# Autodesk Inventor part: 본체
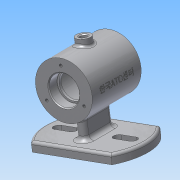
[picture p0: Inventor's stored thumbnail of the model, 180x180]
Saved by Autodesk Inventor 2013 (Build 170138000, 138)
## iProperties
Created: 2017-12
Part Number: 본체
Material: 알루미늄 6061
Document SubType Name: Modeling
Designer: Administrator
Density: 2.71 g/cm^3
Mass: 467.723 g
Surface Area: 486.557 cm^2
Volume: 172.592 cm^3
Author: Administrator
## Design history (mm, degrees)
sketch "스케치1"
  geometry: L1 (-35, -42.426)-(-35, 42.426); L2 (35, -42.426)-(35, 42.426); L3 (0, 0)-(0, 71.634); L4 (5, -40)-(5, -24); L5 (-5, -40)-(-5, -24); L6 (-1.738, 0)-(67.006, 0); L7 (5, 40)-(5, 24); L8 (-5, 40)-(-5, 24); L9 (-15, -5)-(15, -5); L10 (-15, 5)-(15, 5); A1 r 55 centre (0, 0) between (-35, -42.426) and (35, -42.426); A2 r 55 centre (0, 0) between (35, 42.426) and (-35, 42.426); A3 r 5 centre (0, -40) between (-5, -40) and (5, -40); A4 r 5 centre (0, -24) between (5, -24) and (-5, -24); A5 r 5 centre (0, 40) between (5, 40) and (-5, 40); A6 r 5 centre (0, 24) between (-5, 24) and (5, 24); A7 r 5 centre (-15, 0) between (-15, 5) and (-15, -5); A8 r 5 centre (15, 0) between (15, -5) and (15, 5); 1 further point
  constraints: 20 end point, 16 point on circle, 8 centre point, 7 symmetric about line, 4 parallel, 4 tangent, 2 coincident, 2 perpendicular, 1 point on line, 1 vertical, 3 other
  dimensions: "d2" = 70 distance between parallel lines of L2 L1; "d3" = 0 horizontal distance of A4.centre A3.centre; "d4" = 10 diameter of A3; "d5" = 10 diameter of A4; "d6" = 24 distance of point (0, 0) A4.centre; "d7" = 16 distance of A4.centre A3.centre; "d8" = 0 vertical distance of point (0, 0) A7.centre; "d9" = 10 diameter of A7; "d10" = 10 diameter of A8; "d11" = 30 distance of A7.centre A8.centre
extrude "돌출1" new body sketch "스케치1" distance "d12" = 10; taper "d13" = 0 deg
extrude "돌출2" join sketch "스케치1" distance "d14" = 50; taper "d15" = 0 deg
node "스케치2"
sketch "스케치3"
  geometry: L1 (-35, 42.426)-(-35, -42.426) reference; L2 (-5, 40)-(-5, 24); L3 (5, 40)-(5, 24); L4 (0, 0)-(50.574, 0); L5 (-5, -40)-(-5, -24); L6 (5, -40)-(5, -24); A1 r 55 centre (0, 0) between (-35, -42.426) and (35, -42.426) reference; A2 r 5 centre (0, 40) between (5, 40) and (-5, 40) reference; A3 r 5 centre (0, 40) between (5, 40) and (-5, 40); A4 r 5 centre (0, 24) between (-5, 24) and (5, 24); A5 r 5 centre (0, -40) between (-5, -40) and (5, -40); A6 r 5 centre (0, -40) between (-5, -40) and (5, -40); A7 r 5 centre (0, -24) between (5, -24) and (-5, -24)
  constraints: 10 end point, 10 point on circle, 9 symmetric about line, 5 centre point, 2 coincident, 2 parallel, 2 tangent, 1 perpendicular, 3 other
  dimensions: "d16" = 10 diameter of A3; "d18" = 10 diameter of A4; "d19" = 16 distance of A4.centre A3.centre
extrude "돌출3" cut sketch "스케치3" distance "d20" = 50; taper "d21" = 0 deg
sketch "스케치4"
  geometry: L1 (0, -24)-(0, -19) reference; C1 r 30 at (62, 0); 1 further point
  constraints: 1 centre point
  dimensions: "d22" = 0 vertical distance of point (0, 0) C1.centre; "d23" = 60 diameter of C1; "d24" = 62 distance from line of L1 C1.centre
extrude "돌출4" join sketch "스케치4" stored distance "d25" = 70; taper "d26" = 0 deg
sketch "스케치5"
  geometry: C1 r 30 at (0, 0) reference; C2 r 16 at (0, 0); 1 further point
  constraints: 1 centre point, 1 coincident
  dimensions: "d27" = 32 diameter of C2
extrude "돌출5" cut sketch "스케치5" distance "d29" = 12; taper "d30" = 0 deg
sketch "스케치6"
  geometry: C1 r 16 at (0, 0) reference; C2 r 14 at (0, 0); 1 further point
  constraints: 1 centre point, 1 coincident
  dimensions: "d31" = 28 diameter of C2
extrude "돌출6" cut sketch "스케치6" distance "d33" = 3; taper "d34" = 0 deg
hole "구멍1" diameter "d39" = 50; stored, may be unused: countersink angle "d43" = 90 deg, drill point angle "d45" = 0 deg; dims "d37" = 10, "d38" = 10, "d40" = 6, "d41" = 4, "d42" = 2, "d44" = 40
node "작업 평면1"
sketch "스케치8"
  geometry: C1 r 8 at (0, 0); C2 r 4 at (0, 0); 1 further point
  constraints: 2 centre point, 2 coincident
  dimensions: "d47" = 8 diameter of C2; "d49" = 16 diameter of C1
extrude "돌출7" join sketch "스케치8" stored distance "d50" = 40; taper "d51" = 0 deg
extrude "돌출8" cut sketch "스케치8" stored distance "d52" = 40; taper "d53" = 0 deg
sketch "스케치9" dims "d54" = 46
  geometry: C1 r 16 at (0, 0) reference; 3 further points
  constraints: 1 coincident, 1 vertical alignment, 2 other
hole "구멍2" sketch "스케치9" at (0, 23) diameter "d57" = 3.242; stored, may be unused: countersink angle "d61" = 90 deg, drill point angle "d63" = 120 deg; dims "d58" = 8, "d59" = 4, "d60" = 2, "d62" = 10
node "작업 평면2"
sketch "스케치10"
  geometry: L1 (-35, 92)-(-35, 32) reference; 2 further points
  constraints: 1 other
  dimensions: "d68" = 35 distance from line of L1 point (0, 62); "d69" = 30 vertical distance of L1.start point (0, 62)
feature "엠보싱1" sketch "스케치10" dims "d2" = 70, "d3" = 0, "d4" = 10, "d5" = 10, "d6" = 24, "d7" = 16, "d8" = 0, "d9" = 10, "d10" = 10, "d11" = 30, "d12" = 10, "d70" = 0.5, "d71" = 0
fillet "모깎기1" dims "d72" = 5
fillet "모깎기2" dims "d73" = 3
chamfer "모따기1" distance "d74" = 1; stored, may be unused: second distance "d75" = 2, angle "d76" = 45 deg
fillet "모깎기3" dims "d77" = 3
fillet "모깎기4" dims "d78" = 0.3
fillet "모깎기5" dims "d79" = 3
node "솔리드1"
mirror "대칭1"
mirror "대칭2"
pattern_circular "원형 패턴1" dims angle "d65" = 360 deg
mirror "대칭3"
other parameters: "d46" = -99, "d67" = 61
